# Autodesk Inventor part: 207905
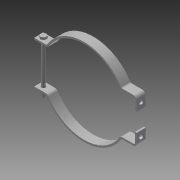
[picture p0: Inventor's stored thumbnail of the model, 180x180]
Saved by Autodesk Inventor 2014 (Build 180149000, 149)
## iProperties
Shininess: 20.0
Length Units: 11272
Angle Units: 11279
Time Units: 11290
Mass Units: 11286
Length Display Precision: 3
Angle Display Precision: 2
Company: Autodesk, Inc.
Created: 2002-06
Part Number: 207905
Material: Steel, Mild
Description: BRACKET ASSY; 221399
Document SubType Name: Modeling
Designer: Autodesk, Inc.
Density: 7.86 g/cm^3
Mass: 743.441 g
Surface Area: 475.09 cm^2
Volume: 94.5854 cm^3
Appearance: Steel
Density: 0.0
Volumn: 0.0
Area: 0.0
PropertySet Name: Model Information
Control State: 0
Master: False
Checked Out: False
Last Check In By: JT
Last Check In Date: 2003-06-20
Title: BRACKET ASSY; 221399
Author: Autodesk, Inc.
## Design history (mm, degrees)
sketch "Sketch1"
  geometry: L1 (-193.794, 0)-(203.14, 0) reference; L2 (0, -23.813)-(0, 142.875) reference; L3 (-105.339, 55.562)-(-137.089, 55.562); L4 (139.7, 25.4)-(139.7, 52.387); L5 (136.525, 55.562)-(105.339, 55.562); L6 (-137.089, 60.325)-(-105.339, 60.325); L7 (105.339, 60.325)-(134.938, 60.325); L8 (144.463, 50.8)-(144.463, 25.4); L9 (-137.089, 55.562)-(-137.089, 60.325); L10 (139.7, 25.4)-(144.463, 25.4); A1 r 114.3 centre (0, 0) between (97.236, 60.081) and (-97.236, 60.081); A2 r 9.525 centre (-105.339, 65.087) between (-105.339, 55.562) and (-97.236, 60.081); A3 r 9.525 centre (105.339, 65.087) between (97.236, 60.081) and (105.339, 55.562); A4 r 4.762 centre (-105.339, 65.087) between (-105.339, 60.325) and (-101.287, 62.584); A5 r 119.062 centre (0, 0) between (101.287, 62.584) and (-101.287, 62.584); A6 r 4.762 centre (105.339, 65.087) between (101.287, 62.584) and (105.339, 60.325); A7 r 3.175 centre (136.525, 52.387) between (139.7, 52.387) and (136.525, 55.562); A8 r 9.525 centre (134.938, 50.8) between (144.463, 50.8) and (134.938, 60.325); 3 further points
  constraints: 16 end point, 16 point on circle, 8 centre point, 8 tangent, 6 perpendicular, 4 point on line, 2 collinear, 1 coincident, 1 equal radius, 1 parallel, 3 other
  dimensions: "d3" = 228.6 diameter of A1; "d17" = 139.7 distance between parallel lines of L4 L2; "d19" = 9.525 radius of A2; "d20" = 4.7625 radial gap between concentric circles of A5 A1; "d42" = 3.175 radius of A7; "d43" = 9.525 radius of A8; "d46" = 31.75 distance from line of L9 A2.centre; "d47" = 4.7625 distance between parallel lines of L8 L4; "d48" = 60.325 distance from line of A1.centre L7
extrude "Extrusion2" new body sketch "Sketch1" stored distance "d22" = 25.4; taper "d23" = 0 deg
mirror "Mirror1"
sketch "Sketch2"
  geometry: L1 (0, 19.05)-(0, 0) reference; 3 further points
  constraints: 1 vertical alignment
  dimensions: "d25" = 12.7 distance from line of point (12.7, 15.875) L1; "d49" = 82.55 distance of point (12.7, -66.675) point (12.7, 15.875); "d50" = 41.275 distance of point (12.7, -25.4) point (12.7, 15.875)
hole "Hole1" sketch "Sketch2" at (12.7, 15.875), (12.7, -66.675) diameter "d26" = 11.1125; stored, may be unused: countersink angle "d30" = 82 deg, drill point angle "d32" = 118 deg; dims "d27" = 12.7, "d28" = 9.525, "d29" = 6.35, "d31" = 19.05
sketch "Sketch3"
  geometry: L1 (0, 0)-(31.75, 0) reference; L2 (0, 0)-(0, 25.4) reference; 1 further point
  dimensions: "d33" = 12.7 distance from line of L1 point (12.7, 12.7); "d34" = 12.7 distance from line of point (12.7, 12.7) L2
hole "Hole2" sketch "Sketch3" at (12.7, 12.7) diameter "d35" = 11.1125; stored, may be unused: countersink angle "d39" = 82 deg, drill point angle "d41" = 118 deg; dims "d36" = 12.7, "d37" = 9.525, "d38" = 6.35, "d40" = 19.05
sketch "Sketch4"
  geometry: L1 (19.844, 8.576)-(12.7, 4.451); L2 (12.7, 4.451)-(5.556, 8.576); L3 (5.556, 8.576)-(5.556, 16.824); L4 (5.556, 16.824)-(12.7, 20.949); L5 (12.7, 20.949)-(19.844, 16.824); L6 (19.844, 16.824)-(19.844, 8.576); C1 r 5.556 at (12.7, 12.7) reference; 1 further point
  constraints: 12 end point, 1 coincident, 1 vertical, 11 other
  dimensions: "d51" = 14.2875 distance between parallel lines of L3 L6
extrude "Extrusion3" join sketch "Sketch4" distance "d52" = 6.35; taper "d53" = 0 deg
sketch "Sketch5"
  geometry: C1 r 5.556 at (0, 0) reference; C2 r 4.763 at (0, 0)
  constraints: 1 centre point, 1 coincident
  dimensions: "d54" = 9.525 diameter of C2
extrude "Extrusion4" join sketch "Sketch5" distance "d55" = 139.7; taper "d56" = 0 deg
sketch "Sketch6"
  geometry: L1 (5.556, -16.824)-(5.556, -8.576); L2 (5.556, -8.576)-(12.7, -4.451); L3 (12.7, -4.451)-(19.844, -8.576); L4 (19.844, -8.576)-(19.844, -16.824); L5 (19.844, -16.824)-(12.7, -20.949); L6 (12.7, -20.949)-(5.556, -16.824); C1 r 5.556 at (12.7, -12.7) reference; 1 further point
  constraints: 12 end point, 1 coincident, 1 vertical, 11 other
  dimensions: "d57" = 14.2875 distance between parallel lines of L4 L1
extrude "Extrusion5" join sketch "Sketch6" distance "d58" = 7.9375; taper "d59" = 0 deg
body "Solid1"
